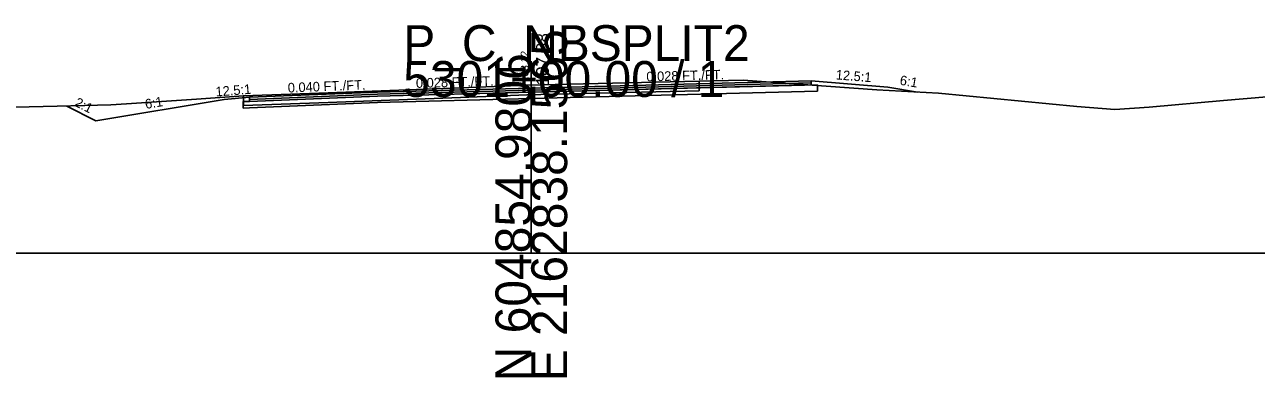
# Model space of a CAD drawing. Extents: x -26 to 1303, y -10 to 12038.
# Drawn here: x 110.4 to 206.6, y 10990.3 to 11017.8 of the extents above; entities that cross this region are included whole.
import ezdxf

# ---------------------------------------------------------------- set-up
doc = ezdxf.new("R2010")
doc.units = 0
for name, color, linetype in [('RD_GPK_XS_Cell', 7, 'Continuous'), ('RD_XS_Base', 7, 'Continuous'), ('RD_XS_ExGround', 7, 'Continuous'), ('RD_XS_ExPaveRet', 7, 'Continuous'), ('RD_XS_Greenside', 7, 'Continuous'), ('RD_XS_Pave', 7, 'Continuous'), ('RD_XS_PaveOvlay_CP', 7, 'Continuous'), ('RD_XS_TieSlope', 7, 'Continuous'), ('RD_XS_TX_Elev_EX', 7, 'Continuous'), ('RD_XS_TX_Elev_PR', 7, 'Continuous'), ('RD_XS_TX_ShdSlope', 7, 'Continuous'), ('RD_XS_TX_Slope', 7, 'Continuous')]:
    doc.layers.add(name, color=color, linetype=linetype)

msp = doc.modelspace()

# ---------------------------------------------------------------- linework, layer by layer
at = {"layer": 'RD_GPK_XS_Cell'}
for p, q in [((150, 11000), (150, 11015)), ((0, 11000), (150, 11000)), ((150, 11000), (300, 11000))]:
    msp.add_line(p, q, dxfattribs=at)
at = {"layer": 'RD_XS_Base'}
for p, q in [((150, 11012.564), (172.353, 11013.145)), ((171.853, 11013.132), (171.853, 11013.132)), ((172.353, 11013.145), (172.353, 11012.645)), ((172.353, 11013.112), (172.353, 11013.112)), ((128, 11011.852), (127.5, 11011.832)), ((127.5, 11011.832), (127.5, 11011.832)), ((127.5, 11011.832), (127.5, 11011.332)), ((138, 11012.252), (128, 11011.852)), ((128, 11011.852), (128, 11011.852)), ((150, 11012.564), (138, 11012.252)), ((138, 11012.252), (138, 11012.252)), ((138, 11011.752), (150, 11012.064)), ((150, 11012.064), (150, 11012.723)), ((150, 11012.723), (150, 11012.723)), ((150, 11012.723), (150, 11012.723)), ((150, 11012.723), (150, 11012.564)), ((172.353, 11012.645), (150, 11012.064)), ((150, 11012.564), (150, 11012.564)), ((150, 11012.064), (150, 11012.564)), ((150, 11012.564), (150, 11012.564)), ((150, 11012.564), (150, 11012.564)), ((150, 11012.064), (150, 11012.064)), ((127.5, 11011.332), (128, 11011.352)), ((128, 11011.352), (138, 11011.752)), ((128, 11011.352), (128, 11011.352)), ((138, 11011.752), (138, 11011.752))]:
    msp.add_line(p, q, dxfattribs=at)
at = {"layer": 'RD_XS_ExGround'}
msp.add_lwpolyline([(107.51, 11011.351), (115.138, 11011.518), (116.105, 11011.545), (117.163, 11011.574), (118.381, 11011.666), (123.848, 11012.018), (127.509, 11012.288), (134.14, 11012.525), (144.475, 11012.917), (147.743, 11013.047), (149.644, 11013.122), (152.952, 11013.186), (163.099, 11013.429), (166.547, 11013.499), (176.977, 11012.755), (181.809, 11012.495), (192.606, 11011.459), (195.579, 11011.214), (198.255, 11011.397), (204.079, 11011.914), (210.83, 11012.5)], dxfattribs=at)
at = {"layer": 'RD_XS_ExPaveRet'}
for points in [[(163.099, 11013.429), (163.099, 11013.429), (163.099, 11012.679), (163.099, 11012.679), (152.952, 11012.436), (152.952, 11012.436), (149.644, 11012.372), (149.644, 11012.372), (147.743, 11012.297), (147.743, 11012.297), (147.743, 11012.297), (144.475, 11012.167), (144.475, 11012.167), (134.14, 11011.775), (134.14, 11011.775), (127.509, 11011.538), (127.509, 11011.538), (127.509, 11011.538), (127.509, 11012.288), (127.509, 11012.288), (127.509, 11012.288), (127.509, 11012.288), (134.14, 11012.525), (134.14, 11012.525), (144.475, 11012.917), (144.475, 11012.917), (147.743, 11013.047), (147.743, 11013.047), (147.743, 11013.047), (149.644, 11013.122), (149.644, 11013.122), (152.952, 11013.186), (152.952, 11013.186), (163.099, 11013.429), (163.099, 11013.429)], [(152.952, 11013.186), (149.644, 11013.122), (147.743, 11013.047), (144.475, 11012.917), (134.14, 11012.525), (127.509, 11012.288), (127.509, 11011.538), (134.14, 11011.775), (144.475, 11012.167), (147.743, 11012.297), (149.644, 11012.372), (152.952, 11012.436), (163.099, 11012.679), (163.099, 11013.429), (152.952, 11013.186)]]:
    msp.add_lwpolyline(points, dxfattribs=at)
at = {"layer": 'RD_XS_Greenside'}
for p, q in [((177.853, 11012.97), (180.177, 11012.583)), ((126, 11012.01), (116, 11010.343)), ((116, 11010.343), (113.712, 11011.487))]:
    msp.add_line(p, q, dxfattribs=at)
at = {"layer": 'RD_XS_Pave'}
for p, q in [((150, 11012.882), (138, 11012.57)), ((171.853, 11013.45), (150, 11012.882)), ((171.853, 11013.291), (150, 11012.723)), ((150, 11012.723), (171.853, 11013.291)), ((150, 11012.564), (171.853, 11013.132)), ((150, 11012.882), (150, 11012.882)), ((171.853, 11013.291), (171.853, 11013.45)), ((171.853, 11013.45), (171.853, 11013.45)), ((171.853, 11013.132), (171.853, 11013.291)), ((171.853, 11013.291), (171.853, 11013.291)), ((138, 11012.57), (128, 11012.17)), ((128, 11012.011), (138, 11012.411)), ((138, 11012.411), (128, 11012.011)), ((128, 11011.852), (138, 11012.252)), ((128, 11012.17), (128, 11012.17)), ((128, 11012.17), (128, 11012.011)), ((128, 11012.011), (128, 11012.011)), ((128, 11012.011), (128, 11011.852)), ((138, 11012.411), (150, 11012.723)), ((150, 11012.723), (138, 11012.411)), ((138, 11012.57), (138, 11012.57)), ((138, 11012.252), (150, 11012.564)), ((138, 11012.411), (138, 11012.411)), ((138, 11012.411), (138, 11012.411)), ((138, 11012.252), (138, 11012.252)), ((150, 11012.723), (150, 11012.723)), ((150, 11012.723), (150, 11012.723)), ((150, 11012.723), (150, 11012.564)), ((150, 11012.723), (150, 11012.723)), ((150, 11012.564), (150, 11012.723)), ((150, 11012.723), (150, 11012.723)), ((150, 11012.723), (150, 11012.723)), ((150, 11012.564), (150, 11012.564)), ((150, 11012.564), (150, 11012.564))]:
    msp.add_line(p, q, dxfattribs=at)
at = {"layer": 'RD_XS_PaveOvlay_CP'}
for p, q in [((150, 11012.882), (138, 11012.57)), ((171.853, 11013.45), (150, 11012.882)), ((150, 11012.882), (150, 11012.882)), ((138, 11012.57), (128, 11012.17)), ((138, 11012.57), (138, 11012.57))]:
    msp.add_line(p, q, dxfattribs=at)
at = {"layer": 'RD_XS_TieSlope'}
for p, q in [((171.853, 11013.45), (177.853, 11012.97)), ((128, 11012.17), (126, 11012.01))]:
    msp.add_line(p, q, dxfattribs=at)

# ---------------------------------------------------------------- texts
at = {"layer": 'RD_GPK_XS_Cell'}
for s, p in [('P_C_NBSPLIT2', (140, 11015)), ('5301+00.00 / 1', (140, 11012.2))]:
    msp.add_text(s, height=2.8, dxfattribs=at).set_placement(p)
for s, p in [('E 2162838.1565', (152.8, 10990)), ('N 604854.9806', (150, 10990))]:
    msp.add_text(s, height=2.8, rotation=90, dxfattribs=at).set_placement(p)
at = {"layer": 'RD_XS_TX_Elev_EX'}
msp.add_text('108.12', height=0.6, rotation=90, dxfattribs=at).set_placement((149.774, 11013.343))
at = {"layer": 'RD_XS_TX_Elev_PR'}
msp.add_text('107.88', height=1, rotation=90, dxfattribs=at).set_placement((151.377, 11013.092))
at = {"layer": 'RD_XS_TX_ShdSlope'}
for rotation, p in [(355.42608, (173.761, 11013.57)), (4.57392, (125.367, 11012.227))]:
    msp.add_text('12.5:1', height=0.75, rotation=rotation, dxfattribs=at).set_placement(p)
at = {"layer": 'RD_XS_TX_Slope'}
for s, rotation, p in [('0.028 FT./FT.', 1.60386, (140.999, 11012.902)), ('0.028 FT./FT.', 1.60386, (158.999, 11013.406)), ('6:1', 350.53582, (178.741, 11013.155)), ('0.040 FT./FT.', 2.29061, (130.995, 11012.538)), ('2:1', 333.43495, (114.259, 11011.524)), ('6:1', 9.46418, (119.893, 11011.258))]:
    msp.add_text(s, height=0.75, rotation=rotation, dxfattribs=at).set_placement(p)

doc.saveas('drawing.dxf')
